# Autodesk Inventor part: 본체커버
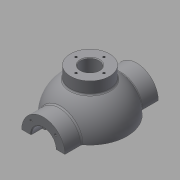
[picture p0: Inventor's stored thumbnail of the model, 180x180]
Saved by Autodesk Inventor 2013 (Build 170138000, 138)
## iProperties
Created: 2015-12
Part Number: 본체커버
Material: 일반
Document SubType Name: Modeling
Designer: mduedu
Density: 2.71 g/cm^3
Mass: 574.351 g
Surface Area: 450.515 cm^2
Volume: 211.938 cm^3
Author: mduedu
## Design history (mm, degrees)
sketch "스케치1"
  geometry: L1 (-53, 0)-(53, 0); A1 r 53 centre (0, 0) between (53, 0) and (-53, 0); 2 further points
  constraints: 2 coincident, 2 end point, 2 point on circle, 1 centre point, 1 horizontal, 1 midpoint
  dimensions: "d0" = 53 radius of A1
revolve "회전1" sketch "스케치1" stored, may be unused: angle "d2" = 90 deg
feature "쉘1" dims "d11" = 10
node "작업 평면1"
sketch "스케치2"
  geometry: C1 r 31 at (0, 0); 1 further point
  constraints: 1 centre point, 1 coincident
  dimensions: "d4" = 62 diameter of C1
extrude "돌출1" join sketch "스케치2" stored distance "d5" = 10; taper "d6" = 0 deg
hole "구멍1" diameter "d14" = 35; stored, may be unused: countersink angle "d18" = 90 deg, drill point angle "d20" = 0 deg; dims "d12" = 10, "d13" = 10, "d15" = 6, "d16" = 4, "d17" = 2, "d19" = 16
hole "구멍2" diameter "d23" = 27; stored, may be unused: countersink angle "d27" = 90 deg, drill point angle "d29" = 0 deg; dims "d21" = 10, "d22" = 10, "d24" = 6, "d25" = 4, "d26" = 2, "d28" = 16
fillet "모깎기1" dims "d30" = 0.3
chamfer "모따기1" distance "d40" = 1; stored, may be unused: second distance "d41" = 2, angle "d42" = 45 deg
sketch "스케치4"
  geometry: L1 (0, 0)-(0, -25); L2 (0, 0)-(-17.678, -17.678); A1 r 25 centre (0, 0) between (-17.678, -17.678) and (0, -25); 1 further point
  constraints: 4 end point, 2 point on circle, 1 centre point, 1 coincident, 1 vertical
  dimensions: "d43" = 50 diameter of A1; "d47" = 45 deg angle of L1 L2
hole "구멍4" sketch "스케치4" at (-17.678, -17.678) diameter "d49" = 3.242; stored, may be unused: countersink angle "d53" = 90 deg, drill point angle "d55" = 118 deg; dims "d50" = 11, "d51" = 4, "d52" = 2, "d54" = 13
node "작업 평면3"
sketch "스케치6"
  geometry: C1 r 65 at (0, 0); 1 further point
  constraints: 1 centre point, 1 coincident
  dimensions: "d78" = 130 diameter of C1
extrude "돌출3" join sketch "스케치6" distance "d80" = 10; taper "d81" = 0 deg
sketch "스케치7"
  geometry: C1 r 20 at (0, 0); 1 further point
  constraints: 1 centre point, 1 coincident
  dimensions: "d82" = 40 diameter of C1
extrude "돌출4" join sketch "스케치7" stored distance "d84" = 10; taper "d85" = 0 deg
sketch "스케치8"
  geometry: 2 further points
  constraints: 1 coincident
hole "구멍6" sketch "스케치8" at (0, 0) diameter "d86" = 20; stored, may be unused: countersink angle "d90" = 90 deg, drill point angle "d92" = 118 deg; dims "d87" = 7, "d88" = 40, "d89" = 5, "d91" = 10
fillet "모깎기2" dims "d93" = 0.3
sketch "스케치9"
  geometry: L1 (65, -75)-(-65, -75) reference; L2 (-45, -75)-(-38.245, -36.692); A1 r 53 centre (0, 0) between (42.988, 31) and (42.988, -31) reference; 1 further point
  constraints: 2 end point, 1 point on circle, 1 point on line
  dimensions: "d94" = 45 horizontal distance of L2.start point (0, 0); "d95" = 80 deg angle of L2 L1
feature "리브1" sketch "스케치9" dims "d96" = 1, "d97" = 8, "d98" = 0, "d99" = 0, "d100" = 1, "d101" = 1
sketch "스케치10"
  geometry: L1 (0, 0)-(0, -55); L2 (0, 0)-(-38.891, -38.891); A1 r 55 centre (0, 0) between (0, -55) and (-38.891, -38.891); 2 further points
  constraints: 4 end point, 2 coincident, 2 point on circle, 1 centre point, 1 vertical
  dimensions: "d105" = 110 diameter of A1; "d107" = 45 deg angle of L1 L2
hole "구멍7" sketch "스케치10" at (-38.891, -38.891) diameter "d109" = 10; stored, may be unused: countersink angle "d113" = 90 deg, drill point angle "d115" = 118 deg; dims "d110" = 7, "d111" = 40, "d112" = 5, "d114" = 10
fillet "모깎기3" dims "d120" = 3
fillet "모깎기4" dims "d121" = 3, "d122" = 3
fillet "모깎기5" dims "d123" = 3
fillet "모깎기6" dims "d124" = 3
sketch "스케치11"
  geometry: C1 r 5 at (-38.891, 38.891) reference; C2 r 5 at (38.891, 38.891) reference; C3 r 5 at (38.891, -38.891) reference; C4 r 5 at (-38.891, -38.891) reference; C5 r 20 at (0, 0) reference; C6 r 65 at (0, 0) reference; 1 further point
  constraints: 3 other
feature "엠보싱1" sketch "스케치11" dims "d125" = 0.5, "d126" = 0
sketch "스케치12"
  geometry: L1 (0, 100)-(0, -100); L2 (0, 100)-(-150, 100); L3 (-150, 100)-(-150, -100); L4 (-150, -100)-(0, -100); 2 further points
  constraints: 8 end point, 3 perpendicular, 1 coincident, 1 midpoint, 1 vertical
  dimensions: "d127" = 200 distance of L2.end L3.end; "d129" = 150 distance of L3.end L1.end
extrude "돌출5" cut sketch "스케치12" stored distance "d130" = 10; taper "d131" = 0 deg
node "작업 평면4"
sketch "스케치16"
  geometry: C1 r 28 at (0, 0); 1 further point
  constraints: 1 centre point, 1 coincident
  dimensions: "d148" = 56 diameter of C1
extrude "돌출9" join sketch "스케치16" stored distance "d150" = 5; taper "d151" = 0 deg
hole "구멍8" diameter "d154" = 26; stored, may be unused: countersink angle "d158" = 90 deg, drill point angle "d160" = 118 deg; dims "d152" = 10, "d153" = 10, "d155" = 6, "d156" = 4, "d157" = 2, "d159" = 8
sketch "스케치17" dims "d161" = 40
  geometry: 3 further points
  constraints: 2 vertical alignment, 1 coincident, 2 other
hole "구멍9" sketch "스케치17" at (0, 20) diameter "d163" = 3.242; stored, may be unused: countersink angle "d167" = 90 deg, drill point angle "d169" = 118 deg; dims "d164" = 8, "d165" = 4, "d166" = 2, "d168" = 10
fillet "모깎기11" dims "d173" = 3
chamfer "모따기2" distance "d174" = 1; stored, may be unused: second distance "d175" = 2, angle "d176" = 45 deg
node "솔리드1"
mirror "대칭1"
mirror "대칭2"
pattern_circular "원형 패턴1" dims angle "d57" = 360 deg
mirror "대칭3"
pattern_circular "원형 패턴3" dims angle "d103" = 360 deg
pattern_circular "원형 패턴4" dims "d40" = 1, angle "d118" = 360 deg
pattern_circular "원형 패턴5" dims angle "d171" = 360 deg
node "투영된 루프1"
other parameters: "d3" = 67, "d77" = -85, "d147" = 62
